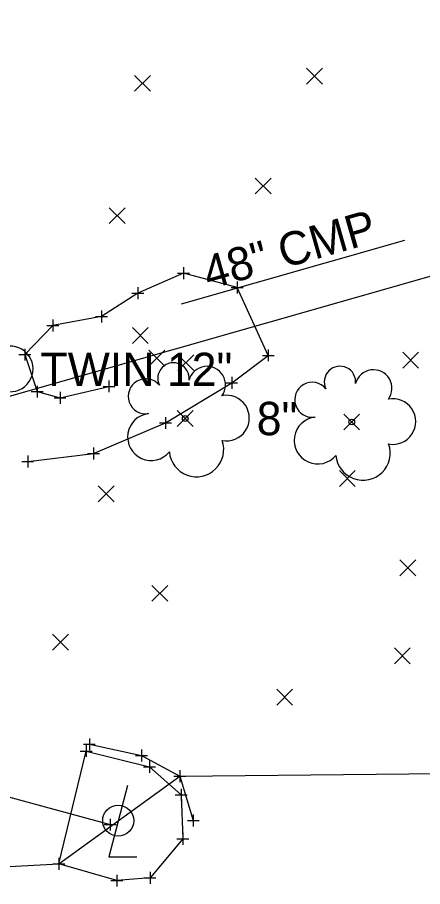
# Model space of a CAD drawing. Extents: x 160138 to 160780, y 488720 to 491073.
# Drawn here: x 160501.3 to 160535.3, y 489628.6 to 489701.6 of the extents above; entities that cross this region are included whole.
import ezdxf

# ---------------------------------------------------------------- set-up
doc = ezdxf.new("R2010")
doc.units = 0
for name, color, linetype in [('_CIVIL_CONSTRUCTION', 7, 'Continuous'), ('DR_X_Storm_Sewer', 7, 'Continuous'), ('DR_X_Text', 7, 'Continuous'), ('RD_X_Concrete_Pad', 7, 'Continuous'), ('RD_X_Wall', 7, 'Continuous'), ('RW_X_Esmt_LA', 7, 'Continuous'), ('SC_Scratch1', 7, 'Continuous'), ('SV_P_Control_Cells_Set', 7, 'Continuous'), ('SV_X_Random_Point', 7, 'Continuous'), ('SV_X_Terrain_Boundary', 7, 'Continuous'), ('UT_X_Electric', 7, 'Continuous'), ('VG_X_Text', 7, 'Continuous')]:
    doc.layers.add(name, color=color, linetype=linetype)

msp = doc.modelspace()

# ---------------------------------------------------------------- linework, layer by layer
at = {"layer": '_CIVIL_CONSTRUCTION'}
for p, q in [((160511.106, 489695.401), (160512.439, 489696.736)), ((160511.106, 489696.736), (160512.439, 489695.401)), ((160525.547, 489695.994), (160526.88, 489697.329)), ((160525.547, 489697.329), (160526.88, 489695.994)), ((160521.236, 489686.78), (160522.57, 489688.115)), ((160521.236, 489688.115), (160522.57, 489686.78)), ((160508.995, 489684.289), (160510.328, 489685.624)), ((160508.995, 489685.624), (160510.328, 489684.289)), ((160510.928, 489674.231), (160512.261, 489675.566)), ((160510.928, 489675.566), (160512.261, 489674.231)), ((160512.313, 489672.318), (160513.647, 489673.653)), ((160512.313, 489673.653), (160513.647, 489672.318)), ((160514.747, 489671.949), (160516.08, 489673.284)), ((160514.747, 489673.284), (160516.08, 489671.949)), ((160533.607, 489672.158), (160534.941, 489673.493)), ((160533.607, 489673.493), (160534.941, 489672.158)), ((160514.694, 489667.256), (160516.027, 489668.591)), ((160514.694, 489668.591), (160516.027, 489667.256)), ((160528.662, 489666.964), (160529.996, 489668.299)), ((160528.662, 489668.299), (160529.996, 489666.964)), ((160528.292, 489662.223), (160529.625, 489663.558)), ((160528.292, 489663.558), (160529.625, 489662.223)), ((160508.057, 489660.929), (160509.39, 489662.264)), ((160508.057, 489662.264), (160509.39, 489660.929)), ((160533.377, 489654.718), (160534.71, 489656.053)), ((160533.377, 489656.053), (160534.71, 489654.718)), ((160512.565, 489652.581), (160513.898, 489653.916)), ((160512.565, 489653.916), (160513.898, 489652.581)), ((160504.233, 489648.483), (160505.566, 489649.818)), ((160504.233, 489649.818), (160505.566, 489648.483)), ((160532.91, 489647.328), (160534.244, 489648.663)), ((160532.91, 489648.663), (160534.244, 489647.328)), ((160523.037, 489643.864), (160524.37, 489645.199)), ((160523.037, 489645.199), (160524.37, 489643.864))]:
    msp.add_line(p, q, dxfattribs=at)
at = {"layer": 'DR_X_Storm_Sewer'}
msp.add_line((160564.265, 489687.947), (160487.37, 489666.011), dxfattribs=at)
at = {"layer": 'DR_X_Text'}
msp.add_line((160515.052, 489677.556), (160533.775, 489682.897), dxfattribs=at)
at = {"layer": 'RD_X_Concrete_Pad'}
msp.add_lwpolyline([(160504.758, 489630.54), (160507.06, 489640.007), (160512.365, 489638.689), (160515.027, 489636.32), (160515.152, 489632.641), (160512.408, 489629.353), (160509.619, 489629.123)], close=True, dxfattribs=at)
at = {"layer": 'RD_X_Wall'}
msp.add_lwpolyline([(160507.32, 489640.571), (160511.693, 489639.624), (160514.912, 489637.894), (160516.04, 489634.17)], dxfattribs=at)
at = {"layer": 'RW_X_Esmt_LA'}
msp.add_lwpolyline([(160510.524, 489637.115), (160508.949, 489631.13), (160511.312, 489631.13)], dxfattribs=at)
msp.add_circle((160509.737, 489634.161), 1.3, dxfattribs=at)
at = {"layer": 'SC_Scratch1'}
for centre in [(160515.36, 489667.924), (160529.329, 489667.631)]:
    msp.add_circle(centre, 0.24, dxfattribs=at)
for centre, radius, start, end in [((160500.678, 489672.086), 1.915, 259.14531, 101.45961), ((160514.377, 489671.291), 1.317, 354.0047, 205.97412), ((160517.186, 489670.753), 1.553, 323.82996, 165.0376), ((160528.345, 489670.999), 1.317, 354.0047, 205.97412), ((160531.155, 489670.46), 1.553, 323.82996, 165.0376), ((160512.051, 489669.788), 1.471, 39.06254, 279.54124), ((160526.019, 489669.495), 1.471, 39.06254, 279.54124), ((160518.821, 489667.96), 1.915, 259.14531, 101.45961), ((160532.789, 489667.667), 1.915, 259.14531, 101.45961), ((160512.507, 489666.375), 1.974, 96.17219, 320.57371), ((160526.475, 489666.083), 1.974, 96.17219, 320.57371), ((160516.307, 489665.319), 2.284, 184.94757, 19.45715), ((160530.275, 489665.026), 2.284, 184.94757, 19.45715)]:
    msp.add_arc(centre, radius, start, end, dxfattribs=at)
at = {"layer": 'SV_P_Control_Cells_Set'}
msp.add_lwpolyline([(160502.145, 489664.319), (160507.666, 489664.984), (160513.714, 489667.551), (160519.26, 489670.914), (160522.332, 489673.227), (160519.718, 489678.926), (160515.228, 489680.136), (160511.39, 489678.451), (160508.337, 489676.496), (160504.258, 489675.737), (160501.905, 489673.287), (160502.938, 489670.181), (160504.859, 489669.659), (160508.966, 489670.623)], dxfattribs=at)
at = {"layer": 'SV_X_Random_Point'}
for p, q in [((160515.228, 489680.636), (160515.228, 489679.636)), ((160514.728, 489680.136), (160515.728, 489680.136)), ((160515.228, 489680.136), (160515.228, 489680.136)), ((160519.718, 489679.426), (160519.718, 489678.426)), ((160510.89, 489678.451), (160511.89, 489678.451)), ((160511.39, 489678.951), (160511.39, 489677.951)), ((160511.39, 489678.451), (160511.39, 489678.451)), ((160519.218, 489678.926), (160520.218, 489678.926)), ((160519.718, 489678.926), (160519.718, 489678.926)), ((160508.337, 489676.996), (160508.337, 489675.996)), ((160504.258, 489676.237), (160504.258, 489675.237)), ((160507.837, 489676.496), (160508.837, 489676.496)), ((160508.337, 489676.496), (160508.337, 489676.496)), ((160503.758, 489675.737), (160504.758, 489675.737)), ((160504.258, 489675.737), (160504.258, 489675.737)), ((160501.405, 489673.287), (160502.405, 489673.287)), ((160501.905, 489673.787), (160501.905, 489672.787)), ((160501.905, 489673.287), (160501.905, 489673.287)), ((160522.332, 489673.727), (160522.332, 489672.727)), ((160521.832, 489673.227), (160522.832, 489673.227)), ((160522.332, 489673.227), (160522.332, 489673.227)), ((160508.966, 489671.123), (160508.966, 489670.123)), ((160519.26, 489671.414), (160519.26, 489670.414)), ((160502.938, 489670.681), (160502.938, 489669.681)), ((160508.466, 489670.623), (160509.466, 489670.623)), ((160508.966, 489670.623), (160508.966, 489670.623)), ((160518.76, 489670.914), (160519.76, 489670.914)), ((160519.26, 489670.914), (160519.26, 489670.914)), ((160502.438, 489670.181), (160503.438, 489670.181)), ((160502.938, 489670.181), (160502.938, 489670.181)), ((160504.359, 489669.659), (160505.359, 489669.659)), ((160504.859, 489670.159), (160504.859, 489669.159)), ((160504.859, 489669.659), (160504.859, 489669.659)), ((160513.214, 489667.551), (160514.214, 489667.551)), ((160513.714, 489668.051), (160513.714, 489667.051)), ((160513.714, 489667.551), (160513.714, 489667.551)), ((160507.666, 489665.484), (160507.666, 489664.484)), ((160502.145, 489664.819), (160502.145, 489663.819)), ((160507.166, 489664.984), (160508.166, 489664.984)), ((160507.666, 489664.984), (160507.666, 489664.984)), ((160501.645, 489664.319), (160502.645, 489664.319)), ((160502.145, 489664.319), (160502.145, 489664.319)), ((160506.82, 489640.571), (160507.82, 489640.571)), ((160507.06, 489640.507), (160507.06, 489639.507)), ((160507.32, 489641.071), (160507.32, 489640.071)), ((160507.32, 489640.571), (160507.32, 489640.571)), ((160506.56, 489640.007), (160507.56, 489640.007)), ((160507.06, 489640.007), (160507.06, 489640.007)), ((160511.693, 489640.124), (160511.693, 489639.124)), ((160511.193, 489639.624), (160512.193, 489639.624)), ((160511.693, 489639.624), (160511.693, 489639.624)), ((160512.365, 489639.189), (160512.365, 489638.189)), ((160511.865, 489638.689), (160512.865, 489638.689)), ((160512.365, 489638.689), (160512.365, 489638.689)), ((160514.912, 489638.394), (160514.912, 489637.394)), ((160514.412, 489637.894), (160515.412, 489637.894)), ((160514.912, 489637.894), (160514.912, 489637.894)), ((160515.027, 489636.82), (160515.027, 489635.82)), ((160514.527, 489636.32), (160515.527, 489636.32)), ((160515.027, 489636.32), (160515.027, 489636.32)), ((160516.04, 489634.67), (160516.04, 489633.67)), ((160509.06, 489634.328), (160509.06, 489633.328)), ((160515.54, 489634.17), (160516.54, 489634.17)), ((160516.04, 489634.17), (160516.04, 489634.17)), ((160508.56, 489633.828), (160509.56, 489633.828)), ((160509.06, 489633.828), (160509.06, 489633.828)), ((160515.152, 489633.141), (160515.152, 489632.141)), ((160514.652, 489632.641), (160515.652, 489632.641)), ((160515.152, 489632.641), (160515.152, 489632.641)), ((160504.758, 489631.04), (160504.758, 489630.04)), ((160504.258, 489630.54), (160505.258, 489630.54)), ((160504.758, 489630.54), (160504.758, 489630.54)), ((160509.619, 489629.623), (160509.619, 489628.623)), ((160512.408, 489629.853), (160512.408, 489628.853)), ((160509.119, 489629.123), (160510.119, 489629.123)), ((160509.619, 489629.123), (160509.619, 489629.123)), ((160511.908, 489629.353), (160512.908, 489629.353)), ((160512.408, 489629.353), (160512.408, 489629.353))]:
    msp.add_line(p, q, dxfattribs=at)
at = {"layer": 'SV_X_Terrain_Boundary'}
msp.add_lwpolyline([(160560.406, 489729.318), (160491.054, 489700.611), (160398.91, 489721.406), (160369.477, 489735.484), (160345.102, 489741.595), (160340, 489741.437), (160332.016, 489740.129), (160312.105, 489734.793), (160313.355, 489709.705), (160316.289, 489695.424), (160319.472, 489684.931), (160347.565, 489655.198), (160408.831, 489644.698), (160473.475, 489628.861), (160504.758, 489630.54), (160514.912, 489637.894), (160547.865, 489638.238)], dxfattribs=at)
at = {"layer": 'UT_X_Electric'}
msp.add_lwpolyline([(160482.364, 489701.549), (160470.541, 489670.998), (160466.679, 489661.471), (160465.182, 489654.101), (160468.511, 489649.396), (160472.544, 489645.328), (160478.518, 489642.182), (160484.862, 489640.429), (160509.06, 489633.828)], dxfattribs=at)

# ---------------------------------------------------------------- texts
at = {"layer": 'DR_X_Text'}
msp.add_text('48" CMP', height=2.8, rotation=15.92163, dxfattribs=at).set_placement((160517.335, 489678.728))
at = {"layer": 'VG_X_Text'}
for s, p in [('TWIN 12"', (160503.218, 489670.65)), ('8"', (160521.36, 489666.524))]:
    msp.add_text(s, height=2.8, dxfattribs=at).set_placement(p)

doc.saveas('drawing.dxf')
